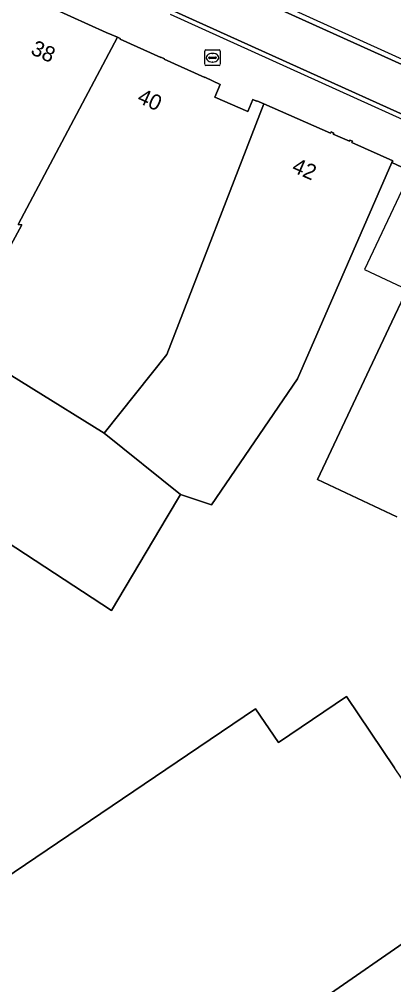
# Model space of a CAD drawing. Extents: x 161087 to 161926, y 382572 to 383873.
# Drawn here: x 161569.9 to 161594, y 382969.9 to 383032.1 of the extents above; entities that cross this region are included whole.
import ezdxf

# ---------------------------------------------------------------- set-up
doc = ezdxf.new("R2010")
doc.units = 0
for name, color, linetype in [('IMGEO_Brandkraan', 7, 'Continuous'), ('IMGEO_Erf', 7, 'Continuous'), ('IMGEO_Lijnafwatering', 7, 'Continuous'), ('IMGEO_Pand', 7, 'Continuous'), ('IMGEO_Pand_nummerreeks', 7, 'Continuous'), ('IMGEO_Pand_overbouw', 7, 'Continuous'), ('IMGEO_Voetgangersgebied_gesloten', 7, 'Continuous'), ('IMGEO_Voetgangersgebied_open', 7, 'Continuous')]:
    doc.layers.add(name, color=color, linetype=linetype)

msp = doc.modelspace()

# ---------------------------------------------------------------- linework, layer by layer
at = {"layer": 'IMGEO_Brandkraan'}
for p, q in [((161581.888, 383029.155), (161581.888, 383030.007)), ((161581.963, 383030.081), (161582.815, 383030.081)), ((161582.376, 383029.861), (161582.401, 383029.861)), ((161582.889, 383030.007), (161582.889, 383029.155)), ((161582.147, 383029.575), (161582.147, 383029.587)), ((161582.585, 383029.538), (161582.187, 383029.538)), ((161582.19, 383029.624), (161582.588, 383029.624)), ((161582.399, 383029.301), (161582.374, 383029.301)), ((161582.631, 383029.587), (161582.631, 383029.575)), ((161582.815, 383029.081), (161581.963, 383029.081))]:
    msp.add_line(p, q, dxfattribs=at)
for points in [[(161581.888, 383029.155), (161581.888, 383030.007)], [(161581.963, 383030.081), (161582.815, 383030.081)], [(161582.889, 383030.007), (161582.889, 383029.155)], [(161582.815, 383029.081), (161581.963, 383029.081)]]:
    msp.add_lwpolyline(points, dxfattribs=at)
for centre, radius, start, end in [((161581.965, 383030.005), 0.0765, 91.55205, 178.44795), ((161581.965, 383030.005), 0.0765, 91.55205, 178.44795), ((161582.813, 383030.005), 0.0765, 1.55205, 88.44795), ((161582.813, 383030.005), 0.0765, 1.55205, 88.44795), ((161581.965, 383029.157), 0.0765, 181.55205, 268.44795), ((161581.965, 383029.157), 0.0765, 181.55205, 268.44795), ((161582.187, 383029.584), 0.0403, 85.87752, 175.75265), ((161582.184, 383029.574), 0.0366, 178.93798, 274.71019), ((161582.588, 383029.581), 0.043, 264.86636, 352.45326), ((161582.592, 383029.586), 0.0386, 1.73085, 96.63898), ((161582.813, 383029.157), 0.0765, 271.55205, 358.44795), ((161582.813, 383029.157), 0.0765, 271.55205, 358.44795)]:
    msp.add_arc(centre, radius, start, end, dxfattribs=at)
for centre, major_axis, ratio, start_param, end_param in [((161582.375, 383029.581), (-0.387, 0.002), 0.722429, 4.712389, 7.853982), ((161582.4, 383029.581), (-0.39, 0.002), 0.717154, 1.570796, 4.712389)]:
    msp.add_ellipse(centre, major_axis=major_axis, ratio=ratio, start_param=start_param, end_param=end_param, dxfattribs=at)
at = {"layer": 'IMGEO_Erf'}
for points in [[(161597.828, 383020.995), (161593.938, 383022.832), (161587.851, 383008.898), (161582.318, 383000.765), (161580.327, 383001.446), (161579.468, 383000), (161575.886, 382993.971), (161566.661, 383000)], [(161594.251, 383000), (161589.147, 383002.399), (161593.731, 383012.151), (161594.908, 383014.656)], [(161563.345, 382972.863), (161580.766, 382984.658), (161585.154, 382987.629), (161586.629, 382985.452), (161591.004, 382988.414), (161594.11, 382983.821)]]:
    msp.add_lwpolyline(points, dxfattribs=at)
at = {"layer": 'IMGEO_Lijnafwatering'}
for points in [[(161581.487, 383035.465), (161605.679, 383024.464)], [(161579.66, 383032.393), (161606.673, 383020.138)]]:
    msp.add_lwpolyline(points, dxfattribs=at)
at = {"layer": 'IMGEO_Pand'}
for points in [[(161576.262, 383030.9), (161575.547, 383031.212), (161570.995, 383033.272), (161570.587, 383033.451), (161569.414, 383033.985), (161569.171, 383034.097), (161563.704, 383025.027), (161561.953, 383022.515), (161557.33, 383016.61), (161565.997, 383011.229), (161570.113, 383018.818), (161569.874, 383018.833)], [(161585.68, 383026.607), (161585.231, 383026.803), (161585.21, 383026.789), (161584.978, 383026.882), (161584.651, 383026.118), (161582.527, 383027.029), (161582.883, 383027.861), (161581.902, 383028.328), (161581.881, 383028.3), (161579.28, 383029.492), (161579.288, 383029.52), (161579.066, 383029.624), (161579.051, 383029.6), (161576.438, 383030.787), (161576.442, 383030.821), (161576.262, 383030.9), (161569.874, 383018.833), (161570.113, 383018.818), (161565.997, 383011.229), (161575.407, 383005.388), (161579.438, 383010.459)], [(161593.938, 383022.832), (161593.989, 383022.936), (161591.361, 383024.112), (161591.397, 383024.195), (161591.234, 383024.266), (161591.206, 383024.202), (161590.161, 383024.658), (161590.189, 383024.723), (161590.024, 383024.795), (161589.992, 383024.721), (161585.68, 383026.607), (161579.438, 383010.459), (161575.407, 383005.388), (161580.327, 383001.446), (161582.318, 383000.765), (161587.851, 383008.898)], [(161565.997, 383011.229), (161557.33, 383016.61), (161551.459, 383009.111), (161551.772, 383008.876), (161548.669, 383004.751), (161544.33, 383000.038), (161550.888, 382994.702), (161555.2, 383000), (161559.179, 383004.89), (161566.661, 383000), (161575.886, 382993.971), (161579.468, 383000), (161580.327, 383001.446), (161575.407, 383005.388)], [(161596.885, 382974.069), (161597.056, 382974.958), (161596.207, 382976.223), (161597.827, 382977.334), (161598.13, 382976.907), (161598.547, 382977.195), (161595.775, 382981.359), (161594.11, 382983.821), (161591.004, 382988.414), (161586.629, 382985.452), (161585.154, 382987.629), (161580.766, 382984.658), (161563.345, 382972.863), (161562.436, 382974.206), (161557.958, 382971.175), (161558.868, 382969.831), (161555.831, 382967.775), (161562.07, 382958.504), (161565.172, 382960.605), (161569.003, 382955.037), (161585.959, 382966.519), (161585.082, 382967.815), (161587.158, 382969.221), (161588.035, 382967.925)]]:
    msp.add_lwpolyline(points, close=True, dxfattribs=at)
msp.add_lwpolyline([(161594.908, 383014.656), (161593.731, 383012.151), (161589.147, 383002.399), (161594.251, 383000)], dxfattribs=at)
at = {"layer": 'IMGEO_Pand_overbouw'}
msp.add_lwpolyline([(161597.271, 383019.756), (161594.585, 383021.02), (161592.171, 383015.943), (161594.908, 383014.656)], close=True, dxfattribs=at)
at = {"layer": 'IMGEO_Voetgangersgebied_gesloten'}
for points in [[(161492.002, 383082.168), (161528.822, 383060.639), (161530.386, 383059.686), (161562.264, 383041.226), (161568.118, 383038.081), (161573.744, 383035.403), (161610.121, 383018.913)], [(161606.751, 383023.646), (161581.31, 383035.152), (161574.303, 383038.328)]]:
    msp.add_lwpolyline(points, dxfattribs=at)
at = {"layer": 'IMGEO_Voetgangersgebied_open'}
for points in [[(161610.121, 383018.913), (161573.744, 383035.403), (161568.118, 383038.081), (161562.264, 383041.226), (161530.386, 383059.686), (161528.822, 383060.639), (161492.002, 383082.168)], [(161574.303, 383038.328), (161581.31, 383035.152), (161606.751, 383023.646)], [(161570.995, 383033.272), (161575.547, 383031.212), (161576.262, 383030.9), (161576.442, 383030.821), (161576.438, 383030.787), (161579.051, 383029.6), (161579.066, 383029.624), (161579.288, 383029.52), (161579.28, 383029.492), (161581.881, 383028.3), (161581.902, 383028.328), (161582.883, 383027.861), (161582.527, 383027.029), (161584.651, 383026.118), (161584.978, 383026.882), (161585.21, 383026.789), (161585.231, 383026.803), (161585.68, 383026.607), (161589.992, 383024.721), (161590.024, 383024.795), (161590.189, 383024.723), (161590.161, 383024.658), (161591.206, 383024.202), (161591.234, 383024.266), (161591.397, 383024.195), (161591.361, 383024.112), (161593.989, 383022.936), (161593.938, 383022.832), (161597.828, 383020.995)], [(161597.767, 382964.102), (161611.79, 382971.239), (161610.18, 382973.67), (161610.014, 382973.921), (161608.386, 382976.347), (161608.225, 382976.596), (161605.048, 382981.518), (161603.453, 382980.439), (161604.416, 382979.02), (161596.885, 382974.069), (161588.035, 382967.925)]]:
    msp.add_lwpolyline(points, dxfattribs=at)

# ---------------------------------------------------------------- texts
at = {"layer": 'IMGEO_Pand_nummerreeks'}
for s, rotation, p in [('38', 335.71805, (161570.615, 383029.842)), ('40', 335.50605, (161577.473, 383026.736)), ('42', 336.39987, (161587.429, 383022.253))]:
    msp.add_text(s, height=1, rotation=rotation, dxfattribs=at).set_placement(p)

doc.saveas('drawing.dxf')
